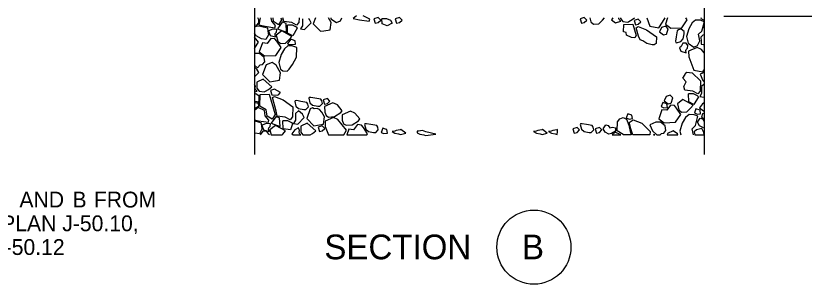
# Model space of a CAD drawing. Extents: x 99862 to 103151, y 100000 to 108153.
# Drawn here: x 100674 to 101472, y 101246 to 101518 of the extents above; entities that cross this region are included whole.
import ezdxf

# ---------------------------------------------------------------- set-up
doc = ezdxf.new("R2010")
doc.units = 0
for name, color, linetype in [('Level 15', 7, 'Continuous'), ('Level 20', 7, 'Continuous'), ('Level 9', 7, 'Continuous')]:
    doc.layers.add(name, color=color, linetype=linetype)

msp = doc.modelspace()

# ---------------------------------------------------------------- linework, layer by layer
at = {"layer": 'Level 15'}
for points in [[(101370.73, 101887.78), (101370.73, 101714.5), (101386.22, 101714.5), (101355.24, 101683.53), (101370.73, 101683.53), (101370.73, 101377.32)], [(100915.73, 101527.63), (100915.73, 101377.32)], [(101390.66, 101517.27), (101545.73, 101517.27)]]:
    msp.add_lwpolyline(points, dxfattribs=at)
at = {"layer": 'Level 20'}
for p, q in [((101296.61, 101397.32), (101288.86, 101397.32)), ((101315.7, 101397.32), (101298.54, 101397.32))]:
    msp.add_line(p, q, dxfattribs=at)
for points in [[(101018.84, 101517.59), (101015.64, 101515.03), (101022.02, 101513.66), (101031.86, 101512.11), (101032.45, 101514.4), (101025.48, 101517.62)], [(101040.86, 101510.77), (101043.37, 101513.29), (101040.86, 101515.8), (101036.57, 101514.47), (101037.9, 101510.18), (101037.9, 101510.18), (101040.86, 101510.77)], [(101062.44, 101510.77), (101064.95, 101513.29), (101062.44, 101515.8), (101058.16, 101514.47), (101059.49, 101510.18), (101059.49, 101510.18), (101062.44, 101510.77)], [(101249.35, 101510.77), (101251.87, 101513.29), (101249.35, 101515.8), (101245.07, 101514.47), (101246.4, 101510.18), (101246.4, 101510.18), (101249.35, 101510.77)], [(100915.73, 101508.09), (100916.51, 101508.49), (100918.1, 101508.15), (100920.21, 101510.7), (100920.02, 101513.7), (100918.94, 101515.66)], [(100921.57, 101515.66), (100920.04, 101508.49), (100926.42, 101507.12), (100936.26, 101505.57), (100936.85, 101507.86), (100933.07, 101512.24), (100932.52, 101515.66)], [(100942.44, 101515.66), (100943.04, 101513.51), (100939.94, 101508.63), (100935.06, 101511.74), (100934.42, 101515.66)], [(100960.8, 101515.66), (100960.57, 101510.95), (100958.21, 101508.1), (100953.35, 101510.84), (100945.26, 101511.89), (100944.31, 101515.66)], [(100949.74, 101508.4), (100953.67, 101508.38), (100957.72, 101506.63), (100958.97, 101505.22), (100954.47, 101497.32), (100949.24, 101500.24), (100949, 101508.11), (100949.74, 101508.4)], [(100964.16, 101514.62), (100964.12, 101507.63), (100962.26, 101504.53), (100966.4, 101503.7), (100973.03, 101510.4), (100971.19, 101513.87), (100970.3, 101514.62)], [(100977.43, 101515.66), (100975.02, 101509.4), (100982.41, 101502.01), (100985.96, 101502.6), (100992.12, 101503.63), (100993.2, 101511.03), (100990.53, 101515.66)], [(100992.78, 101515.66), (100993.01, 101514.77), (100998.77, 101510.92), (101002.69, 101512.62), (101004.2, 101515.66)], [(101044.76, 101509.57), (101044.6, 101514.65), (101045.34, 101514.94)], [(101045.34, 101514.94), (101049.27, 101514.92), (101053.32, 101513.17), (101054.87, 101510.32), (101050.06, 101507.47), (101044.98, 101509.69)], [(101255.01, 101515.66), (101255.98, 101511.7), (101258.75, 101509.22), (101263.93, 101509.67), (101265, 101510.59), (101267.66, 101513.25), (101269.67, 101515.66)], [(101278.37, 101515.66), (101276.84, 101513.57), (101280.86, 101510.61), (101286.29, 101512.27), (101284.63, 101513.97), (101284.22, 101515.07), (101284.35, 101515.66)], [(101286.05, 101515.66), (101286.06, 101515.11), (101288.19, 101512.07), (101293.33, 101511.32), (101294.58, 101511.97), (101297.78, 101513.96), (101300.05, 101515.66)], [(101289.16, 101501.58), (101289.41, 101508.79), (101298.57, 101509.09), (101301.78, 101497.74)], [(101303.95, 101509.12), (101306.47, 101511.63), (101303.95, 101514.14), (101299.67, 101512.81), (101301, 101508.52), (101301, 101508.52), (101303.95, 101509.12)], [(101312.59, 101515.66), (101315.76, 101507.14), (101324.85, 101505.59), (101328.55, 101511.36), (101331.31, 101515.66)], [(101333.57, 101515.66), (101331.36, 101509.14), (101336.75, 101505.07), (101348.06, 101505.59), (101353.52, 101513.58), (101352.08, 101515.66)], [(101370.73, 101511.65), (101367.02, 101513.24), (101361.95, 101513.28), (101358.4, 101510.48), (101355, 101504.56), (101352.63, 101496.58), (101354.33, 101489.86), (101360.1, 101486.01), (101364.02, 101487.71), (101366.38, 101492.44), (101364.9, 101498.95), (101368.3, 101502.2), (101370.54, 101510.51), (101370.73, 101511.39)], [(101367.47, 101515.66), (101367.24, 101514.99), (101367.24, 101514.99), (101369.96, 101513.71)], [(101369.96, 101513.71), (101370.73, 101513.82)], [(100915.73, 101506.58), (100918.56, 101507.38), (100921.89, 101507.16), (100928.69, 101505.38), (100929.21, 101501.98), (100929.72, 101498.58), (100927.21, 101493.78), (100922.78, 101494.52), (100917.38, 101497.47), (100915.73, 101500.02)], [(101301.78, 101497.74), (101300.56, 101495.34), (101297, 101495.59), (101292.05, 101498.07), (101291.77, 101500.85), (101289.16, 101501.58)], [(101304.06, 101496.96), (101301.86, 101505.62), (101303.85, 101506.81), (101312.45, 101503.49), (101322.41, 101496.29), (101322.08, 101489.68)], [(101332.58, 101498.92), (101334.22, 101504.55), (101331.7, 101507.06), (101327.42, 101505.73), (101325.42, 101501.45), (101329.36, 101498.39), (101332.32, 101498.98)], [(101344.71, 101503.5), (101343.17, 101502.47), (101342.32, 101496.47), (101341.64, 101492.17), (101341.82, 101490.5), (101342.57, 101490.23)], [(101342.57, 101490.23), (101347.12, 101491.51), (101349.51, 101494.36), (101350.36, 101499.56), (101350.25, 101501.67), (101347.5, 101504.24), (101344.71, 101503.5)], [(101370.73, 101505.36), (101370.59, 101505.6), (101370.73, 101505.81)], [(100915.73, 101484.54), (100916.15, 101485.2), (100919.85, 101490.96), (100915.73, 101496.12)], [(100953.7, 101488.48), (100957.22, 101489), (100956.7, 101492.51), (100952.47, 101494), (100949.06, 101489.76), (100949.95, 101488.51), (100953.7, 101488.48)], [(101322.08, 101489.68), (101321.95, 101489.74), (101319.99, 101488.26), (101318.01, 101488.45), (101312.66, 101489.75), (101308.58, 101492.4), (101306.04, 101493.37), (101304.06, 101496.96)], [(101370.73, 101498.29), (101369.45, 101498.02), (101367.16, 101495.95), (101367.67, 101492.04), (101367.53, 101488.86), (101370.7, 101488.71), (101370.73, 101488.72)], [(100958.39, 101485.47), (100954.62, 101487.08), (100949.55, 101487.13), (100946, 101484.32), (100942.6, 101478.41), (100940.24, 101470.42), (100941.94, 101463.7), (100944.49, 101462)], [(100944.45, 101462.13), (100948.83, 101461.76), (100950.84, 101463.78), (100954.26, 101468.28), (100958.14, 101475.91), (100958.39, 101485.47)], [(101345.72, 101485.36), (101347.1, 101481.75), (101352.56, 101480.21), (101352.08, 101482.53), (101352.34, 101483.68), (101353.75, 101485.08), (101354.04, 101487.74), (101352.58, 101489.91), (101349.21, 101490.09)], [(101349.21, 101490.09), (101347.39, 101486.5), (101345.72, 101485.36)], [(101370.73, 101480.16), (101367.98, 101483.6), (101363.4, 101485.52), (101354.9, 101481.75), (101355.19, 101476.29), (101360.29, 101462.61), (101369.38, 101461.06), (101370.73, 101463.16)], [(101370.73, 101486.94), (101370.65, 101487.64), (101370.73, 101487.66)], [(100915.73, 101467.75), (100918.89, 101465.02), (100921.53, 101468.08), (100923.91, 101468.42), (100925.98, 101471.23), (100925.39, 101475.66), (100920.66, 101479.51), (100915.93, 101479.51), (100915.73, 101479.42)], [(100915.73, 101456.05), (100920, 101460.36), (100918.15, 101463.83), (100915.73, 101465.9)], [(101350.18, 101446.14), (101351.52, 101448.71), (101352.3, 101450.82), (101349.2, 101454.65), (101351.31, 101458.13), (101351.66, 101459.67), (101352.94, 101460.52)], [(101352.94, 101460.52), (101358.54, 101459.9), (101366.94, 101451.76), (101366.43, 101441.51), (101364.07, 101438.66), (101359.21, 101441.4), (101351.12, 101442.45), (101350.18, 101446.14)], [(101370.73, 101460.22), (101366.65, 101458.47), (101369.31, 101452.27), (101370.73, 101451.04)], [(100915.73, 101440.76), (100918.42, 101441.59), (100916.76, 101443.28), (100916.36, 101444.39), (100916.78, 101446.33), (100915.73, 101448.43)], [(101370.73, 101448.66), (101368.05, 101446.28), (101368.02, 101439.23), (101366.15, 101436.12), (101370.29, 101435.29), (101370.73, 101435.73)], [(100915.73, 101431.32), (100918.1, 101430.99), (100920.06, 101430.14), (100920.54, 101432.84), (100920.32, 101436.39), (100917.07, 101438.68), (100915.73, 101438.24)], [(100939.51, 101437.42), (100942.02, 101439.94), (100936.09, 101443.45), (100931.8, 101442.12), (100933.13, 101437.84), (100933.13, 101437.84), (100939.39, 101437.37)], [(101337.28, 101429.13), (101338.92, 101434.76), (101336.4, 101437.27), (101332.12, 101435.94), (101330.11, 101431.66), (101334.06, 101428.59), (101337.02, 101429.18)], [(101355.6, 101438.96), (101359.53, 101438.93), (101363.58, 101437.19), (101364.83, 101435.78), (101360.33, 101427.88), (101355.1, 101430.8), (101354.86, 101438.67), (101355.6, 101438.96)], [(100915.73, 101429.78), (100916.66, 101430.07), (100919.51, 101429.22), (100919.73, 101425.89), (100915.73, 101423.52)], [(100969.64, 101428.4), (100968.66, 101429.97), (100962.7, 101431.02), (100958.42, 101431.84), (100956.74, 101431.71), (100956.45, 101430.97)], [(100956.45, 101430.97), (100957.58, 101426.38), (100960.35, 101423.9), (100965.52, 101422.88), (100967.63, 101422.92), (100970.29, 101425.58), (100969.64, 101428.4)], [(100983.79, 101431.64), (100982.81, 101433.22), (100976.85, 101434.27), (100972.57, 101435.09), (100970.89, 101434.96), (100970.6, 101434.22)], [(100970.6, 101434.22), (100971.73, 101429.63), (100974.5, 101427.15), (100979.67, 101426.13), (100981.79, 101426.17), (100984.45, 101428.83), (100983.79, 101431.64)], [(100989.53, 101428.94), (100992.04, 101431.45), (100989.53, 101433.96), (100985.24, 101432.63), (100986.57, 101428.35), (100986.57, 101428.35), (100989.53, 101428.94)], [(101004.33, 101421.68), (100999.55, 101427.67), (100994.97, 101429.59), (100986.47, 101425.82), (100986.76, 101420.35), (100988.07, 101416.84)], [(101329.94, 101424.47), (101333.46, 101424.99), (101332.94, 101428.5), (101328.7, 101429.99), (101327.22, 101425.76), (101327.22, 101425.76), (101329.94, 101424.47)], [(101370.73, 101429.47), (101368.86, 101428.54), (101365.9, 101424.51), (101369.92, 101421.55), (101370.73, 101421.8)], [(100915.73, 101412.41), (100919.88, 101411.52), (100929.72, 101409.97), (100930.31, 101412.26), (100926.53, 101416.64), (100925.7, 101421.83), (100919.27, 101424.86), (100915.73, 101421.86)], [(100974.49, 101424.45), (100972.18, 101423.41), (100968.48, 101413.8), (100975.87, 101406.41), (100979.42, 101407), (100985.58, 101408.03), (100986.66, 101415.43), (100983.83, 101420.33)], [(100983.83, 101420.33), (100981.62, 101422.81), (100978.99, 101423.98), (100976.2, 101423.61), (100974.49, 101424.45)], [(100988.07, 101416.84), (100990.61, 101415.28), (100996.76, 101415.71), (101003.06, 101419.89), (101004.33, 101421.68)], [(101022.12, 101413.35), (101017.34, 101419.34), (101012.75, 101421.26), (101004.25, 101417.49), (101004.55, 101412.02), (101005.86, 101408.51)], [(101363.42, 101418.11), (101366.94, 101418.63), (101366.42, 101422.14), (101362.18, 101423.63), (101360.7, 101419.39), (101360.7, 101419.39), (101363.42, 101418.11)], [(101005.97, 101397.32), (101008.91, 101401.9), (101000.11, 101412.91), (100995.53, 101414.84), (100987.03, 101411.07), (100987.33, 101405.6), (100990.41, 101397.32)], [(101005.86, 101408.51), (101008.4, 101406.95), (101014.55, 101407.38), (101020.84, 101411.56), (101022.12, 101413.35)], [(101282.78, 101410.58), (101285.33, 101413.44), (101288.55, 101414.87), (101292.05, 101413.08), (101292.14, 101413.1)], [(101294.61, 101413.1), (101298.12, 101413.62), (101297.6, 101417.13), (101293.37, 101418.62), (101291.88, 101414.38), (101291.88, 101414.38), (101294.61, 101413.1)], [(101292.14, 101413.1), (101294.45, 101406.98), (101295.69, 101400.55), (101296.61, 101397.32)], [(101298.54, 101397.32), (101296.29, 101403.19), (101294.6, 101409.84), (101298.93, 101412.39), (101307.53, 101409.07), (101315.87, 101400.69), (101315.7, 101397.32)], [(101364.24, 101416.03), (101360.48, 101417.64), (101355.41, 101417.69), (101351.86, 101414.88), (101348.46, 101408.96), (101346.1, 101400.98), (101347.02, 101397.32)], [(101359.73, 101397.32), (101358.36, 101403.35), (101361.76, 101406.6), (101364, 101414.91), (101364.24, 101416.03)], [(101370.73, 101404.65), (101369.89, 101404.46), (101366.05, 101406.45), (101364.05, 101410), (101366.68, 101414.03), (101368.97, 101413.29), (101370.71, 101410.81), (101370.73, 101410.82)], [(101370.73, 101419.22), (101368.9, 101418.61), (101367.93, 101414.99), (101370.73, 101413.43)], [(100915.73, 101411.46), (100922.15, 101409.78), (100922.67, 101406.38), (100923.18, 101402.98), (100920.67, 101398.18), (100916.24, 101398.92), (100915.73, 101399.2)], [(100943.6, 101397.32), (100944.32, 101398.03), (100947, 101401.23), (100936.8, 101406.73), (100931.2, 101402.36), (100932.44, 101397.32)], [(100945.07, 101411.66), (100949, 101411.63), (100953.05, 101409.89), (100954.3, 101408.47), (100952.15, 101402.46), (100944.57, 101403.49), (100944.33, 101411.37), (100945.07, 101411.66)], [(100962.7, 101397.32), (100961.29, 101398.75), (100960.89, 101399.86), (100961.31, 101401.8), (100960.11, 101404.19), (100956.46, 101402.38), (100953.5, 101398.35), (100954.91, 101397.32)], [(100972.15, 101397.32), (100974.44, 101398.74), (100977.78, 101401.24), (100969.11, 101408.93), (100962.66, 101405.94), (100962.72, 101399.89), (100964.53, 101397.32)], [(100984.3, 101401.24), (100986.81, 101403.75), (100984.3, 101406.26), (100980.01, 101404.93), (100981.34, 101400.65), (100981.34, 101400.65), (100984.3, 101401.24)], [(101029.47, 101397.32), (101030.18, 101398.36), (101025.83, 101404.64), (101023.84, 101407.16), (101019.77, 101407.59), (101016, 101402.49), (101011.12, 101403.08), (101009.17, 101397.32)], [(101040.31, 101405.04), (101039.33, 101406.61), (101033.36, 101407.66), (101029.08, 101408.48), (101027.41, 101408.35), (101027.12, 101407.61)], [(101027.12, 101407.61), (101028.24, 101403.02), (101031.01, 101400.54), (101036.19, 101399.52), (101038.3, 101399.57), (101040.96, 101402.23), (101040.31, 101405.04)], [(101242.01, 101399.64), (101244.52, 101402.16), (101242.01, 101404.67), (101237.72, 101403.34), (101239.05, 101399.05), (101239.05, 101399.05), (101242.01, 101399.64)], [(101258.43, 101405.04), (101257.44, 101406.61), (101251.48, 101407.66), (101247.2, 101408.48), (101245.53, 101408.35), (101245.24, 101407.61)], [(101245.24, 101407.61), (101246.36, 101403.02), (101249.13, 101400.54), (101254.31, 101399.52), (101256.42, 101399.57), (101259.08, 101402.23), (101258.43, 101405.04)], [(101264.58, 101399.64), (101267.09, 101402.16), (101264.58, 101404.67), (101260.29, 101403.34), (101261.62, 101399.05), (101261.62, 101399.05), (101264.58, 101399.64)], [(101288.86, 101397.32), (101288.82, 101397.58), (101282.46, 101401.28), (101282.78, 101410.58)], [(101326.24, 101397.32), (101327.39, 101398.64), (101329.77, 101398.98), (101331.84, 101401.79), (101331.25, 101406.22), (101326.52, 101410.07), (101321.79, 101410.07), (101315.58, 101407.4), (101318.24, 101401.2), (101322.73, 101397.32)], [(100930.77, 101397.32), (100930.23, 101398.1), (100928.24, 101400.62), (100924.17, 101401.05), (100921.41, 101397.32)], [(100932.44, 101397.32), (100943.6, 101397.32)], [(100954.91, 101397.32), (100962.7, 101397.32)], [(100964.53, 101397.32), (100972.15, 101397.32)], [(100990.41, 101397.32), (101001.71, 101397.32), (101005.97, 101397.32)], [(101009.17, 101397.32), (101019.84, 101397.32), (101029.47, 101397.32)], [(101046.63, 101398.49), (101050.14, 101399.01), (101049.62, 101402.52), (101048.25, 101403), (101045.39, 101404.01), (101043.9, 101399.78), (101043.9, 101399.78), (101046.63, 101398.49)], [(101054.83, 101400.53), (101057.72, 101398.92), (101061.49, 101398.41), (101063.45, 101397.56), (101068.68, 101398.88), (101063.78, 101402.63)], [(101063.78, 101402.63), (101063.11, 101402.46), (101059.13, 101401.51), (101057.51, 101401.12), (101054.83, 101400.53)], [(101089.17, 101400.4), (101085.7, 101401.76), (101081.72, 101400.82), (101080.32, 101400.84), (101080.22, 101399.45)], [(101080.22, 101399.45), (101083.11, 101397.85), (101086.88, 101397.33), (101088.84, 101396.48), (101099.13, 101397.86), (101089.17, 101400.4)], [(101197.99, 101400.53), (101200.88, 101398.92), (101204.65, 101398.41), (101206.61, 101397.56), (101211.85, 101398.88), (101206.94, 101402.63)], [(101206.94, 101402.63), (101206.28, 101402.46), (101202.3, 101401.51), (101200.68, 101401.12), (101197.99, 101400.53)], [(101213.18, 101400.53), (101216.07, 101398.92), (101219.84, 101398.41), (101221.79, 101397.56), (101222.27, 101400.25), (101222.13, 101402.63)], [(101222.13, 101402.63), (101221.46, 101402.46), (101217.48, 101401.51), (101215.86, 101401.12), (101213.18, 101400.53)], [(101286.18, 101397.32), (101280.59, 101399.95), (101277.49, 101397.32)], [(101277.49, 101397.32), (101286.18, 101397.32)], [(101320.58, 101397.32), (101319.96, 101397.85), (101319.36, 101397.32)], [(101319.36, 101397.32), (101320.58, 101397.32)], [(101322.73, 101397.32), (101326.24, 101397.32)], [(101344.07, 101397.32), (101343.55, 101398.2), (101339.42, 101401.16), (101333.5, 101398.5), (101333.05, 101397.32)], [(101333.05, 101397.32), (101344.07, 101397.32)], [(101370.56, 101397.32), (101370.41, 101399.73), (101368.3, 101403.53), (101362.91, 101402.42), (101360.62, 101400.35), (101361.02, 101397.32)], [(101361.02, 101397.32), (101370.56, 101397.32)]]:
    msp.add_lwpolyline(points, dxfattribs=at)
for points in [[(100943.71, 101511.07), (100939.13, 101504.57), (100948.14, 101501.17), (100947.63, 101509.96), (100944.3, 101511.22), (100944.3, 101511.22)], [(100936.71, 101499.8), (100938.11, 101501.21), (100938.41, 101503.87), (100934.35, 101504.32), (100929.69, 101502.54), (100931.47, 101497.87), (100936.93, 101496.33), (100936.45, 101498.66)], [(100948.2, 101490.97), (100950.86, 101493.63), (100953.54, 101496.83), (100943.34, 101502.33), (100937.74, 101497.96), (100939.18, 101492.08), (100941.95, 101489.6), (100947.13, 101490.05)], [(100928.51, 101489.76), (100923.63, 101490.35), (100920.53, 101481.18), (100925.92, 101477.12), (100937.23, 101477.63), (100942.69, 101485.62), (100938.34, 101491.9), (100936.34, 101494.42), (100932.28, 101494.85)], [(100942.13, 101459.96), (100937.7, 101467.64), (100933.56, 101470.6), (100927.65, 101467.94), (100923.95, 101458.33), (100931.34, 101450.94), (100934.89, 101451.53), (100941.05, 101452.56)], [(100926.72, 101441.29), (100929.91, 101443.27), (100933.25, 101445.77), (100924.58, 101453.46), (100918.13, 101450.47), (100918.19, 101444.42), (100920.32, 101441.38), (100925.46, 101440.63)], [(100921.54, 101438.1), (100930.7, 101438.4), (100936.5, 101417.91), (100933.4, 101413.04), (100928.52, 101416.14), (100927.49, 101422.5), (100921.13, 101426.19)], [(100935.98, 101436.13), (100944.58, 101432.8), (100954.54, 101425.6), (100954.03, 101415.35), (100951.67, 101412.5), (100946.81, 101415.24), (100938.72, 101416.29), (100937.49, 101421.13), (100933.99, 101434.93)], [(101354.06, 101421.53), (101356.72, 101424.19), (101359.4, 101427.39), (101349.2, 101432.89), (101343.6, 101428.51), (101345.04, 101422.64), (101347.81, 101420.16), (101352.99, 101420.61)], [(100966.09, 101414.71), (100964.24, 101418.18), (100960.19, 101421.64), (100957.22, 101419), (100957.18, 101411.94), (100955.31, 101408.83), (100959.46, 101408.01)], [(101332.8, 101422.11), (101327.92, 101422.7), (101324.82, 101413.54), (101330.21, 101409.47), (101341.52, 101409.99), (101346.98, 101417.98), (101342.63, 101424.26), (101340.63, 101426.78), (101336.57, 101427.21)], [(100937.17, 101415.47), (100932.59, 101408.97), (100941.6, 101405.57), (100941.09, 101414.37), (100937.76, 101415.62), (100937.76, 101415.62)], [(100930.17, 101404.2), (100931.57, 101405.61), (100931.87, 101408.27), (100927.81, 101408.72), (100923.15, 101406.94), (100924.93, 101402.27), (100930.39, 101400.73), (100929.91, 101403.06)], [(101277.99, 101405.16), (101280.83, 101404.31), (101281.06, 101400.98), (101276.88, 101398.51), (101274.29, 101397.92), (101270.45, 101399.91), (101268.45, 101403.46), (101271.08, 101407.49), (101273.37, 101406.75), (101275.11, 101404.27)]]:
    msp.add_lwpolyline(points, close=True, dxfattribs=at)
at = {"layer": 'Level 9'}
msp.add_circle((101198.36, 101283.64), 37.5, dxfattribs=at)

# ---------------------------------------------------------------- texts
at = {"layer": 'Level 20'}
for s, height, p in [(' AND ', 16, (100671.9, 101323.76)), ('B', 16, (100731.53, 101323.76)), (' FROM ', 16, (100747.22, 101323.76)), ('STANDARD PLAN J-50.10, ', 16, (100535.71, 101299.76)), ('SECTION', 25, (100986.37, 101271.37)), ('B', 25, (101186.3, 101271.37)), ('J-5-.11, OR J-50.12', 16, (100535.71, 101275.76))]:
    msp.add_text(s, height=height, dxfattribs=at).set_placement(p)

doc.saveas('drawing.dxf')
